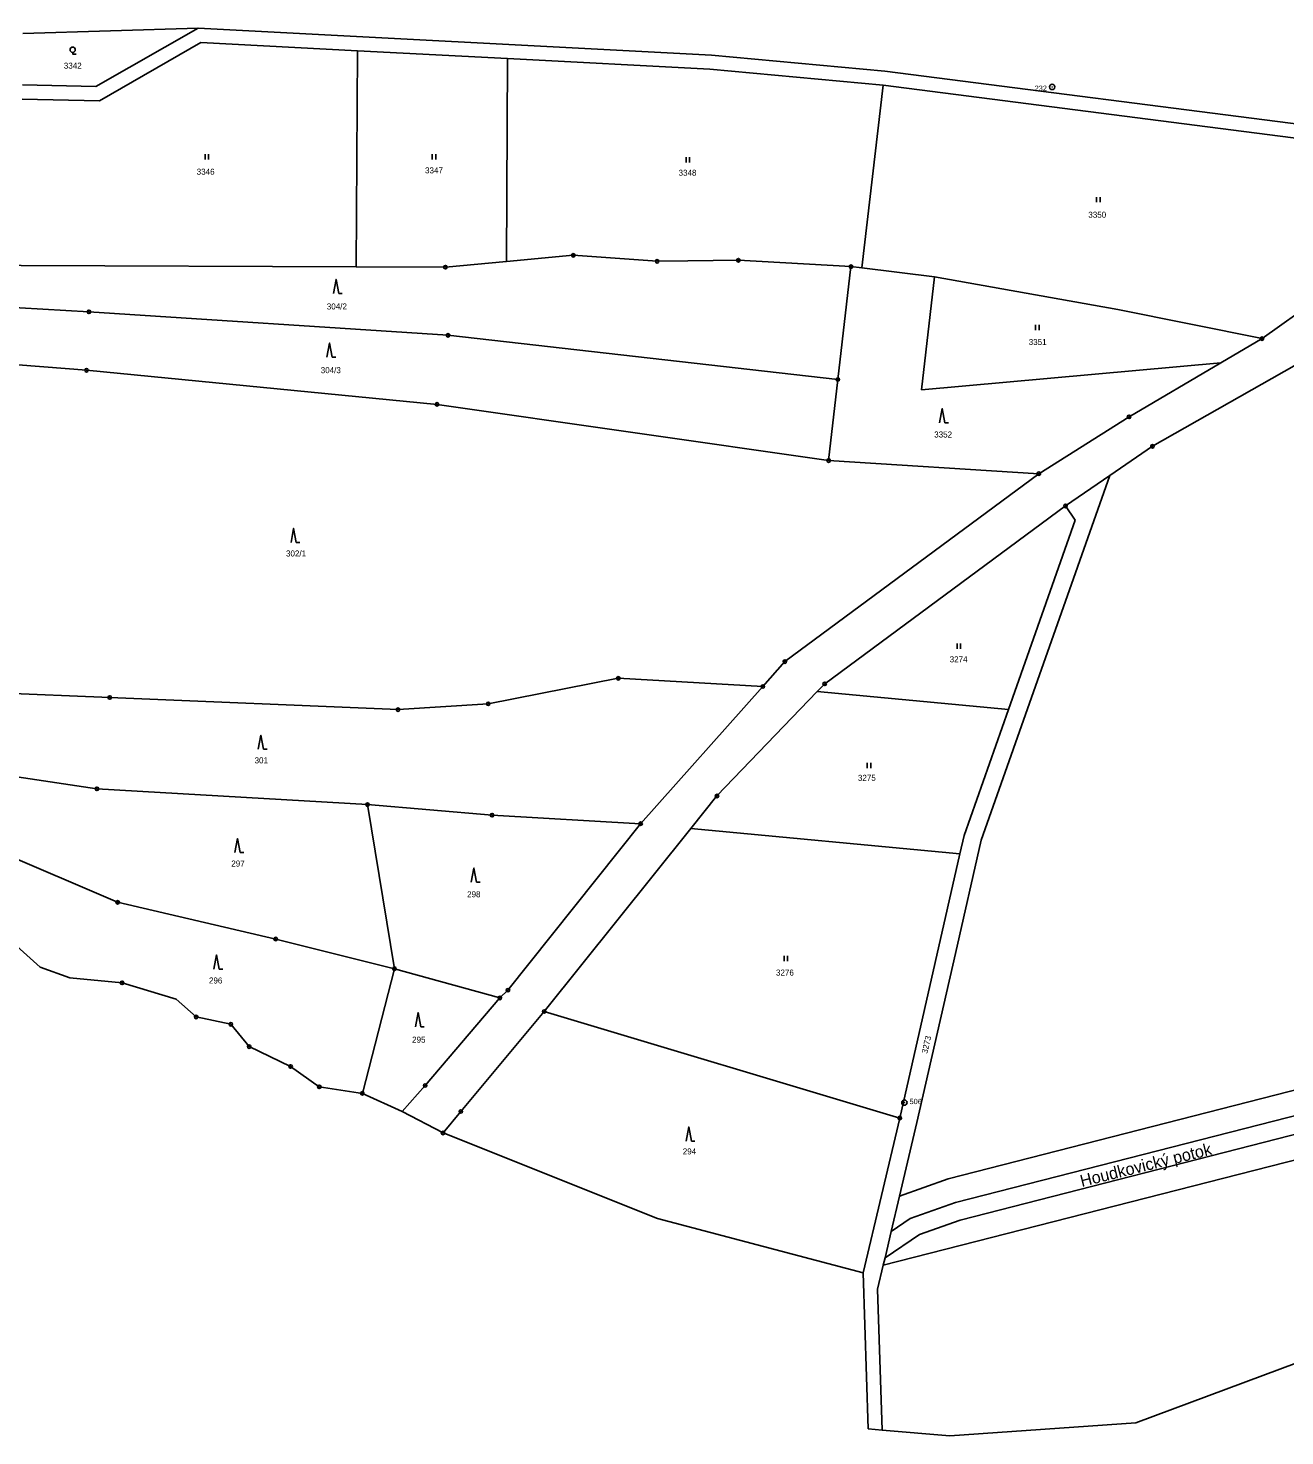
# Model space of a CAD drawing. Extents: x -618848 to -615803, y -1044450 to -1042254.
# Drawn here: x -617807.4 to -617451.9, y -1044450.2 to -1044052.1 of the extents above; entities that cross this region are included whole.
import ezdxf
from ezdxf.enums import TextEntityAlignment as Align

# ---------------------------------------------------------------- set-up
doc = ezdxf.new("R2010")
doc.units = 0
doc.header["$LTSCALE"] = 0.68
for name, color, linetype, lineweight in [('1', 7, 'Continuous', 25), ('3', 7, 'Continuous', 25), ('7', 7, 'Continuous', 13), ('8', 7, 'Continuous', 25)]:
    doc.layers.add(name, color=color, linetype=linetype, lineweight=lineweight)
doc.layers.add('2', color=7, linetype='Continuous')

msp = doc.modelspace()

# ---------------------------------------------------------------- linework, layer by layer
at = {"layer": '1'}
for p, q in [((-617808.93, -1044053.54), (-617759.25, -1044052.05)), ((-617759.25, -1044052.05), (-617788.2, -1044068.54)), ((-617759.25, -1044052.05), (-617614.04, -1044059.7)), ((-617787.18, -1044072.56), (-617758.51, -1044056.09)), ((-617758.51, -1044056.09), (-617714.24, -1044058.42)), ((-617714.24, -1044058.42), (-617714.6, -1044119.56)), ((-617671.73, -1044060.66), (-617714.24, -1044058.42)), ((-617672.07, -1044118.05), (-617671.73, -1044060.66)), ((-617614.5, -1044063.67), (-617671.73, -1044060.66)), ((-617614.04, -1044059.7), (-617565.03, -1044064.17)), ((-617565.49, -1044068.14), (-617614.5, -1044063.67)), ((-617565.03, -1044064.17), (-617402.5, -1044085.04)), ((-617788.2, -1044068.54), (-617809.02, -1044068.1)), ((-617571.51, -1044119.86), (-617565.49, -1044068.14)), ((-617409.75, -1044088.14), (-617565.49, -1044068.14)), ((-617809.04, -1044072.1), (-617787.18, -1044072.56)), ((-617689.35, -1044119.65), (-617672.07, -1044118.05)), ((-617672.07, -1044118.05), (-617653.17, -1044116.3)), ((-617653.17, -1044116.3), (-617629.43, -1044118)), ((-617629.43, -1044118), (-617620.8, -1044117.89)), ((-617620.8, -1044117.89), (-617606.46, -1044117.7)), ((-617606.46, -1044117.7), (-617574.6, -1044119.49)), ((-617714.6, -1044119.56), (-617689.35, -1044119.65)), ((-617574.6, -1044119.49), (-617578.31, -1044151.43)), ((-617574.6, -1044119.49), (-617571.51, -1044119.86)), ((-617571.51, -1044119.86), (-617550.94, -1044122.37)), ((-617554.66, -1044154.38), (-617550.94, -1044122.37)), ((-617550.94, -1044122.37), (-617499.08, -1044131.62)), ((-617790.18, -1044132.28), (-617868.44, -1044127.67)), ((-617458.31, -1044139.86), (-617442.1, -1044128.33)), ((-617688.62, -1044138.93), (-617790.18, -1044132.28)), ((-617499.08, -1044131.62), (-617458.31, -1044139.86)), ((-617870.92, -1044142.59), (-617790.88, -1044148.81)), ((-617578.31, -1044151.43), (-617688.62, -1044138.93)), ((-617489.29, -1044170.32), (-617440.05, -1044142.35)), ((-617458.31, -1044139.86), (-617469.96, -1044146.71)), ((-617469.96, -1044146.71), (-617554.66, -1044154.38)), ((-617495.93, -1044161.97), (-617469.96, -1044146.71)), ((-617790.88, -1044148.81), (-617691.71, -1044158.46)), ((-617580.92, -1044174.36), (-617578.31, -1044151.43)), ((-617691.71, -1044158.46), (-617580.92, -1044174.36)), ((-617521.48, -1044178.07), (-617495.93, -1044161.97)), ((-617501.4, -1044178.61), (-617489.29, -1044170.32)), ((-617580.92, -1044174.36), (-617521.48, -1044178.07)), ((-617521.48, -1044178.07), (-617593.3, -1044231.22)), ((-617537.8, -1044281.68), (-617501.4, -1044178.61)), ((-617501.4, -1044178.61), (-617513.92, -1044187.18)), ((-617582.04, -1044237.5), (-617513.92, -1044187.18)), ((-617513.92, -1044187.18), (-617511.18, -1044191.26)), ((-617511.18, -1044191.26), (-617530.07, -1044244.8)), ((-617593.3, -1044231.22), (-617599.53, -1044238.27)), ((-617784.3, -1044241.37), (-617869.01, -1044237.88)), ((-617640.43, -1044235.95), (-617677.24, -1044243.18)), ((-617599.53, -1044238.27), (-617640.43, -1044235.95)), ((-617599.53, -1044238.27), (-617634.12, -1044277.07)), ((-617584.17, -1044239.71), (-617582.04, -1044237.5)), ((-617702.73, -1044244.79), (-617784.3, -1044241.37)), ((-617612.53, -1044269.21), (-617584.17, -1044239.71)), ((-617530.07, -1044244.8), (-617584.17, -1044239.71)), ((-617677.24, -1044243.18), (-617702.73, -1044244.79)), ((-617542.62, -1044280.37), (-617530.07, -1044244.8)), ((-617849.67, -1044257.87), (-617787.93, -1044267.22)), ((-617787.93, -1044267.22), (-617711.38, -1044271.66)), ((-617619.91, -1044278.42), (-617612.53, -1044269.21)), ((-617711.38, -1044271.66), (-617676.14, -1044274.64)), ((-617711.38, -1044271.66), (-617703.75, -1044318.08)), ((-617676.14, -1044274.64), (-617634.12, -1044277.07)), ((-617634.12, -1044277.07), (-617671.66, -1044324.14)), ((-617782.08, -1044299.3), (-617831.39, -1044278.13)), ((-617661.39, -1044330.18), (-617619.91, -1044278.42)), ((-617619.91, -1044278.42), (-617543.8, -1044285.57)), ((-617545.08, -1044313.74), (-617537.8, -1044281.68)), ((-617543.8, -1044285.57), (-617542.62, -1044280.37)), ((-617560.77, -1044360.31), (-617543.8, -1044285.57)), ((-617737.36, -1044309.7), (-617782.08, -1044299.3)), ((-617703.75, -1044318.08), (-617737.36, -1044309.7)), ((-617555.95, -1044361.62), (-617545.08, -1044313.74)), ((-617795.59, -1044320.64), (-617780.82, -1044322.08)), ((-617703.75, -1044318.08), (-617712.82, -1044353.35)), ((-617673.96, -1044326.35), (-617703.75, -1044318.08)), ((-617780.82, -1044322.08), (-617765.48, -1044326.67)), ((-617671.66, -1044324.14), (-617673.96, -1044326.35)), ((-617765.48, -1044326.67), (-617759.84, -1044331.72)), ((-617695.08, -1044351.1), (-617673.96, -1044326.35)), ((-617759.84, -1044331.72), (-617750.05, -1044333.79)), ((-617750.05, -1044333.79), (-617744.85, -1044340.13)), ((-617684.98, -1044358.47), (-617661.39, -1044330.18)), ((-617661.39, -1044330.18), (-617560.77, -1044360.31)), ((-617744.85, -1044340.13), (-617733.13, -1044345.75)), ((-617733.13, -1044345.75), (-617725.02, -1044351.5)), ((-617547.07, -1044377.5), (-617434.14, -1044348.62)), ((-617725.02, -1044351.5), (-617712.82, -1044353.35)), ((-617712.82, -1044353.35), (-617701.55, -1044358.51)), ((-617701.55, -1044358.51), (-617695.08, -1044351.1)), ((-617432.24, -1044355.35), (-617545.02, -1044384.2)), ((-617701.55, -1044358.51), (-617690, -1044364.55)), ((-617690, -1044364.55), (-617684.98, -1044358.47)), ((-617560.77, -1044360.31), (-617571.19, -1044404.07)), ((-617560.85, -1044382.4), (-617555.95, -1044361.62)), ((-617543.74, -1044389.19), (-617426.93, -1044359.32)), ((-617690, -1044364.55), (-617629.37, -1044388.77)), ((-617436.92, -1044369.09), (-617565.47, -1044401.97)), ((-617560.85, -1044382.4), (-617547.07, -1044377.5)), ((-617563.2, -1044392.39), (-617560.85, -1044382.4)), ((-617545.02, -1044384.2), (-617557.83, -1044388.76)), ((-617629.37, -1044388.77), (-617571.19, -1044404.07)), ((-617557.83, -1044388.76), (-617563.2, -1044392.39)), ((-617555.25, -1044393.28), (-617543.74, -1044389.19)), ((-617564.97, -1044399.86), (-617563.2, -1044392.39)), ((-617564.97, -1044399.86), (-617555.25, -1044393.28)), ((-617565.47, -1044401.97), (-617564.97, -1044399.86)), ((-617571.19, -1044404.07), (-617569.75, -1044448.26)), ((-617567.06, -1044408.76), (-617565.47, -1044401.97)), ((-617567.06, -1044408.76), (-617565.76, -1044448.6)), ((-617493.98, -1044446.51), (-617425.02, -1044420.74)), ((-617569.75, -1044448.26), (-617565.76, -1044448.6)), ((-617565.76, -1044448.6), (-617546.68, -1044450.21)), ((-617546.68, -1044450.21), (-617493.98, -1044446.51))]:
    msp.add_line(p, q, dxfattribs=at)
for points in [[(-617714.6, -1044119.56), (-617809.32, -1044119.2), (-617866.32, -1044112.2)], [(-617818.27, -1044304.96), (-617803.97, -1044317.65), (-617795.59, -1044320.64)]]:
    msp.add_lwpolyline(points, dxfattribs=at)
at = {"layer": '3'}
for p, q in [((-617757.351, -1044089.18), (-617757.351, -1044087.68)), ((-617756.35, -1044089.18), (-617756.35, -1044087.68)), ((-617693.061, -1044089.18), (-617693.061, -1044087.68)), ((-617692.06, -1044089.18), (-617692.06, -1044087.68)), ((-617621.261, -1044090.07), (-617621.261, -1044088.57)), ((-617620.26, -1044090.07), (-617620.26, -1044088.57)), ((-617505.111, -1044101.31), (-617505.111, -1044099.81)), ((-617504.11, -1044101.31), (-617504.11, -1044099.81)), ((-617719.53, -1044127.11), (-617718.534, -1044127.11)), ((-617522.411, -1044137.49), (-617522.411, -1044135.99)), ((-617521.41, -1044137.49), (-617521.41, -1044135.99)), ((-617721.37, -1044145.14), (-617720.374, -1044145.14)), ((-617548.02, -1044163.64), (-617547.024, -1044163.64)), ((-617731.52, -1044197.53), (-617730.524, -1044197.53)), ((-617544.591, -1044227.58), (-617544.591, -1044226.08)), ((-617543.59, -1044227.58), (-617543.59, -1044226.08)), ((-617740.79, -1044256.03), (-617739.794, -1044256.03)), ((-617570.011, -1044261.37), (-617570.011, -1044259.87)), ((-617569.01, -1044261.37), (-617569.01, -1044259.87)), ((-617747.38, -1044285.26), (-617746.384, -1044285.26)), ((-617680.54, -1044293.63), (-617679.544, -1044293.63)), ((-617593.541, -1044315.91), (-617593.541, -1044314.41)), ((-617592.54, -1044315.91), (-617592.54, -1044314.41)), ((-617753.35, -1044318.18), (-617752.354, -1044318.18)), ((-617696.32, -1044334.48), (-617695.324, -1044334.48)), ((-617619.75, -1044366.82), (-617618.754, -1044366.82))]:
    msp.add_line(p, q, dxfattribs=at)
for points in [[(-617794.79, -1044058.902), (-617794.79, -1044059.4), (-617793.789, -1044059.4)], [(-617719.53, -1044127.11), (-617720.28, -1044123.11), (-617721.03, -1044127.11)], [(-617721.37, -1044145.14), (-617722.12, -1044141.14), (-617722.87, -1044145.14)], [(-617548.02, -1044163.64), (-617548.77, -1044159.64), (-617549.52, -1044163.64)], [(-617731.52, -1044197.53), (-617732.27, -1044193.53), (-617733.02, -1044197.53)], [(-617740.79, -1044256.03), (-617741.54, -1044252.03), (-617742.29, -1044256.03)], [(-617747.38, -1044285.26), (-617748.13, -1044281.26), (-617748.88, -1044285.26)], [(-617680.54, -1044293.63), (-617681.29, -1044289.63), (-617682.04, -1044293.63)], [(-617753.35, -1044318.18), (-617754.1, -1044314.18), (-617754.85, -1044318.18)], [(-617696.32, -1044334.48), (-617697.07, -1044330.48), (-617697.82, -1044334.48)], [(-617619.75, -1044366.82), (-617620.5, -1044362.82), (-617621.25, -1044366.82)]]:
    msp.add_lwpolyline(points, dxfattribs=at)
msp.add_circle((-617794.7893, -1044058.1509), 0.75, dxfattribs=at)
at = {"layer": '8'}
for centre, radius in [((-617517.68, -1044068.6898), 0.75), ((-617517.68, -1044068.6898), 0.03), ((-617653.17, -1044116.2999), 0.5), ((-617653.17, -1044116.2999), 0.0303), ((-617629.43, -1044117.9999), 0.5), ((-617629.43, -1044117.9999), 0.0303), ((-617606.46, -1044117.6999), 0.5), ((-617606.46, -1044117.6999), 0.0303), ((-617689.35, -1044119.6499), 0.5), ((-617689.35, -1044119.6499), 0.0303), ((-617574.6, -1044119.4899), 0.5), ((-617574.6, -1044119.4899), 0.0303), ((-617790.18, -1044132.2799), 0.5), ((-617790.18, -1044132.2799), 0.0303), ((-617688.62, -1044138.9299), 0.5), ((-617688.62, -1044138.9299), 0.0303), ((-617458.31, -1044139.8599), 0.5), ((-617458.31, -1044139.8599), 0.0303), ((-617790.88, -1044148.8099), 0.5), ((-617790.88, -1044148.8099), 0.0303), ((-617578.31, -1044151.4299), 0.5), ((-617578.31, -1044151.4299), 0.0303), ((-617691.71, -1044158.4599), 0.5), ((-617691.71, -1044158.4599), 0.0303), ((-617495.93, -1044161.9699), 0.5), ((-617495.93, -1044161.9699), 0.0303), ((-617489.29, -1044170.3199), 0.5), ((-617489.29, -1044170.3199), 0.0303), ((-617580.92, -1044174.3599), 0.5), ((-617580.92, -1044174.3599), 0.0303), ((-617521.48, -1044178.0699), 0.5), ((-617521.48, -1044178.0699), 0.0303), ((-617513.92, -1044187.1799), 0.5), ((-617513.92, -1044187.1799), 0.0303), ((-617593.3, -1044231.2199), 0.5), ((-617593.3, -1044231.2199), 0.0303), ((-617640.43, -1044235.9499), 0.5), ((-617640.43, -1044235.9499), 0.0303), ((-617599.53, -1044238.2699), 0.5), ((-617599.53, -1044238.2699), 0.0303), ((-617582.04, -1044237.4999), 0.5), ((-617582.04, -1044237.4999), 0.0303), ((-617784.3, -1044241.3699), 0.5), ((-617784.3, -1044241.3699), 0.0303), ((-617702.73, -1044244.7899), 0.5), ((-617702.73, -1044244.7899), 0.0303), ((-617677.24, -1044243.1799), 0.5), ((-617677.24, -1044243.1799), 0.0303), ((-617787.93, -1044267.2199), 0.5), ((-617787.93, -1044267.2199), 0.0303), ((-617612.53, -1044269.2099), 0.5), ((-617612.53, -1044269.2099), 0.0303), ((-617711.38, -1044271.6599), 0.5), ((-617711.38, -1044271.6599), 0.0303), ((-617676.14, -1044274.6399), 0.5), ((-617676.14, -1044274.6399), 0.0303), ((-617634.12, -1044277.0699), 0.5), ((-617634.12, -1044277.0699), 0.0303), ((-617782.08, -1044299.2999), 0.5), ((-617782.08, -1044299.2999), 0.0303), ((-617737.36, -1044309.6999), 0.5), ((-617737.36, -1044309.6999), 0.0303), ((-617703.75, -1044318.0799), 0.5), ((-617780.82, -1044322.0799), 0.5), ((-617703.75, -1044318.0799), 0.0303), ((-617780.82, -1044322.0799), 0.0303), ((-617673.96, -1044326.3499), 0.5), ((-617671.66, -1044324.1399), 0.5), ((-617671.66, -1044324.1399), 0.0303), ((-617673.96, -1044326.3499), 0.0303), ((-617661.39, -1044330.1799), 0.5), ((-617759.84, -1044331.7199), 0.5), ((-617759.84, -1044331.7199), 0.0303), ((-617750.05, -1044333.7899), 0.5), ((-617750.05, -1044333.7899), 0.0303), ((-617661.39, -1044330.1799), 0.0303), ((-617744.85, -1044340.1299), 0.5), ((-617744.85, -1044340.1299), 0.0303), ((-617733.13, -1044345.7499), 0.5), ((-617733.13, -1044345.7499), 0.0303), ((-617725.02, -1044351.4999), 0.5), ((-617725.02, -1044351.4999), 0.0303), ((-617712.82, -1044353.3499), 0.5), ((-617712.82, -1044353.3499), 0.0303), ((-617695.08, -1044351.0999), 0.5), ((-617695.08, -1044351.0999), 0.0303), ((-617559.48, -1044355.9598), 0.75), ((-617559.48, -1044355.9598), 0.03), ((-617684.98, -1044358.4699), 0.5), ((-617684.98, -1044358.4699), 0.0303), ((-617560.77, -1044360.3099), 0.5), ((-617560.77, -1044360.3099), 0.0303), ((-617690, -1044364.5499), 0.5), ((-617690, -1044364.5499), 0.0303)]:
    msp.add_circle(centre, radius, dxfattribs=at)

# ---------------------------------------------------------------- texts
at = {"layer": '2'}
for s, p in [('3342', (-617797.29, -1044063.505)), ('3346', (-617759.7, -1044093.505)), ('3347', (-617695.1, -1044093.125)), ('3348', (-617623.38, -1044093.805)), ('3350', (-617507.46, -1044105.675)), ('3351', (-617524.32, -1044141.675)), ('3352', (-617551.06, -1044167.835)), ('3274', (-617546.69, -1044231.415)), ('3275', (-617572.64, -1044264.945)), ('3276', (-617595.82, -1044320.025))]:
    msp.add_text(s, height=1.7, dxfattribs=at).set_placement(p)
for s, p in [('304/2', (-617720.05, -1044131.615)), ('304/3', (-617721.77, -1044149.635)), ('302/1', (-617731.6, -1044201.485)), ('301', (-617741.429, -1044260.005)), ('297', (-617748.019, -1044289.185)), ('298', (-617681.309, -1044297.875)), ('296', (-617754.329, -1044322.265)), ('295', (-617696.869, -1044338.995)), ('294', (-617620.299, -1044370.615))]:
    msp.add_text(s, height=1.7, dxfattribs=at).set_placement(p, align=Align.CENTER)
msp.add_text('3273', height=1.7, rotation=77, dxfattribs=at).set_placement((-617553.005, -1044342.225))
at = {"layer": '7'}
msp.add_text('Houdkovický potok', height=3.4, rotation=14, dxfattribs=at).set_placement((-617490.7943, -1044375.2319), align=Align.CENTER)
at = {"layer": '8'}
msp.add_text('232', height=1.5, dxfattribs=at).set_placement((-617519.179, -1044069.807), align=Align.RIGHT)
msp.add_text('506', height=1.5, dxfattribs=at).set_placement((-617558.02, -1044356.385))

doc.saveas('drawing.dxf')
